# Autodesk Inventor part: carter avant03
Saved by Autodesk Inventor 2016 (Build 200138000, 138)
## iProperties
Created: 2013-10
Part Number: carter avant03
Material: Générique
Document SubType Name: Modeling
Designer: Bruno
Density: 1 g/cm^3
Appearance: Par défaut
Author: Bruno
Sending System: SolidWorks 2013
Last Author: christophe
Last Saved: 2014-02-15
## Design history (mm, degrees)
feature "Congé1"
node "Solide1"
